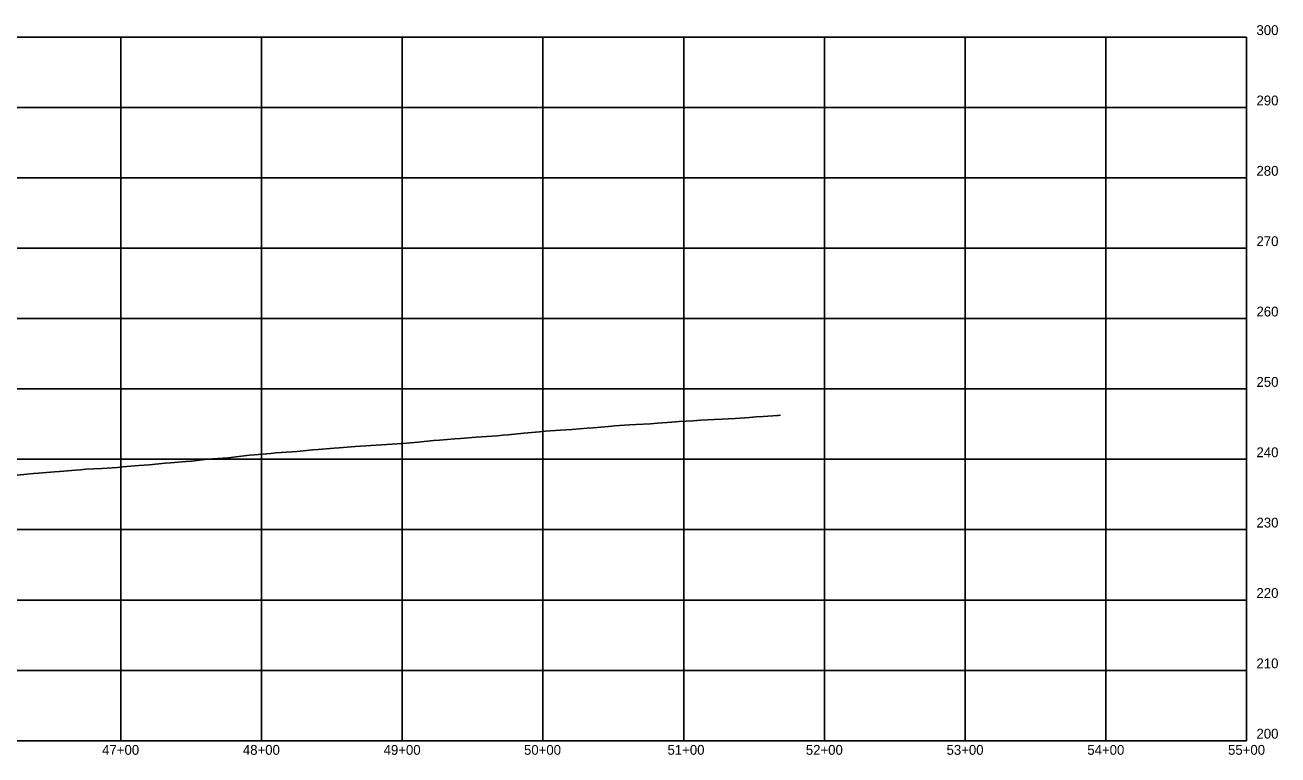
# Model space of a CAD drawing. Extents: x 976639 to 985448, y 1524031 to 1526806.
# Drawn here: x 984558 to 985448, y 1524031 to 1524550 of the extents above; entities that cross this region are included whole.
import ezdxf

# ---------------------------------------------------------------- set-up
doc = ezdxf.new("R2010")
doc.units = 0
for name, color, linetype in [('Default', 7, 'Continuous'), ('R_Axis', 7, 'Continuous'), ('R_Axis Annot', 7, 'Continuous'), ('R_Grid', 7, 'Continuous')]:
    doc.layers.add(name, color=color, linetype=linetype)

msp = doc.modelspace()

# ---------------------------------------------------------------- linework, layer by layer
at = {"layer": 'Default'}
msp.add_lwpolyline([(984552.65, 1524230.09), (984564.28, 1524231.25), (984567.65, 1524231.52), (984579.16, 1524232.52), (984582.65, 1524232.82), (984594, 1524233.75), (984597.65, 1524234.05), (984601.35, 1524234.34), (984612.65, 1524234.97), (984623.87, 1524235.68), (984627.64, 1524235.98), (984638.97, 1524236.92), (984642.75, 1524237.24), (984646.47, 1524237.52), (984657.75, 1524238.56), (984661.47, 1524238.87), (984672.75, 1524239.86), (984676.4, 1524240.19), (984687.75, 1524241.46), (984691.28, 1524241.75), (984702.74, 1524242.51), (984706.3, 1524242.85), (984717.74, 1524244.36), (984721.31, 1524244.64), (984732.74, 1524245.62), (984736.28, 1524245.92), (984747.74, 1524246.73), (984751.33, 1524247.02), (984762.74, 1524248.15), (984766.45, 1524248.41), (984777.73, 1524249.31), (984781.44, 1524249.6), (984792.73, 1524250.55), (984796.45, 1524250.83), (984807.73, 1524251.52), (984811.58, 1524251.8), (984822.62, 1524252.41), (984826.71, 1524252.75), (984837.62, 1524253.51), (984848.47, 1524254.68), (984852.61, 1524255.04), (984863.53, 1524255.87), (984867.61, 1524256.12), (984878.69, 1524257.17), (984882.61, 1524257.45), (984893.75, 1524258.21), (984897.61, 1524258.52), (984901.57, 1524258.83), (984912.61, 1524259.93), (984923.69, 1524260.96), (984927.67, 1524261.3), (984938.66, 1524262.1), (984942.67, 1524262.43), (984946.63, 1524262.71), (984957.66, 1524263.62), (984961.86, 1524263.9), (984972.66, 1524264.81), (984977.07, 1524265.18), (984987.66, 1524265.84), (984992.4, 1524266.19), (985002.66, 1524266.63), (985007.58, 1524267), (985017.66, 1524267.74), (985022.9, 1524268.19), (985032.8, 1524268.8), (985038.33, 1524269.16), (985047.8, 1524269.64), (985053.27, 1524269.94), (985062.8, 1524270.35), (985072.92, 1524271.21), (985077.8, 1524271.52), (985082.72, 1524271.79), (985092.8, 1524272.59), (985093.53, 1524272.63), (985095.04, 1524272.72)], dxfattribs=at)
at = {"layer": 'R_Axis'}
for p, q in [((985426.18, 1524041.42), (985426.18, 1524541.42)), ((982626.18, 1524041.42), (985426.18, 1524041.42))]:
    msp.add_line(p, q, dxfattribs=at)
at = {"layer": 'R_Grid'}
for p, q in [((982626.18, 1524541.42), (985426.18, 1524541.42)), ((982626.18, 1524541.42), (985426.18, 1524541.42)), ((984626.18, 1524041.42), (984626.18, 1524541.42)), ((984726.18, 1524041.42), (984726.18, 1524541.42)), ((984826.18, 1524041.42), (984826.18, 1524541.42)), ((984926.18, 1524041.42), (984926.18, 1524541.42)), ((985026.18, 1524041.42), (985026.18, 1524541.42)), ((985126.18, 1524041.42), (985126.18, 1524541.42)), ((985226.18, 1524041.42), (985226.18, 1524541.42)), ((985326.18, 1524041.42), (985326.18, 1524541.42)), ((982626.18, 1524491.42), (985426.18, 1524491.42)), ((982626.18, 1524441.42), (985426.18, 1524441.42)), ((982626.18, 1524391.42), (985426.18, 1524391.42)), ((982626.18, 1524341.42), (985426.18, 1524341.42)), ((982626.18, 1524291.42), (985426.18, 1524291.42)), ((982626.18, 1524241.42), (985426.18, 1524241.42)), ((982626.18, 1524191.42), (985426.18, 1524191.42)), ((982626.18, 1524141.42), (985426.18, 1524141.42)), ((982626.18, 1524091.42), (985426.18, 1524091.42))]:
    msp.add_line(p, q, dxfattribs=at)

# ---------------------------------------------------------------- texts
at = {"layer": 'R_Axis Annot'}
for s, p in [('300', (985433.18, 1524542.92)), ('300', (985433.18, 1524542.92)), ('290', (985433.18, 1524492.92)), ('280', (985433.18, 1524442.92)), ('270', (985433.18, 1524392.92)), ('260', (985433.18, 1524342.92)), ('250', (985433.18, 1524292.92)), ('240', (985433.18, 1524242.92)), ('230', (985433.18, 1524192.92)), ('220', (985433.18, 1524142.92)), ('210', (985433.18, 1524092.92)), ('200', (985433.18, 1524042.92)), ('47+00', (984612.98, 1524031.42)), ('48+00', (984712.98, 1524031.42)), ('49+00', (984812.98, 1524031.42)), ('50+00', (984912.74, 1524031.42)), ('51+00', (985014.68, 1524031.42)), ('52+00', (985112.98, 1524031.42)), ('53+00', (985212.98, 1524031.42)), ('54+00', (985312.98, 1524031.42)), ('55+00', (985412.98, 1524031.42))]:
    msp.add_text(s, height=7, dxfattribs=at).set_placement(p)

doc.saveas('drawing.dxf')
